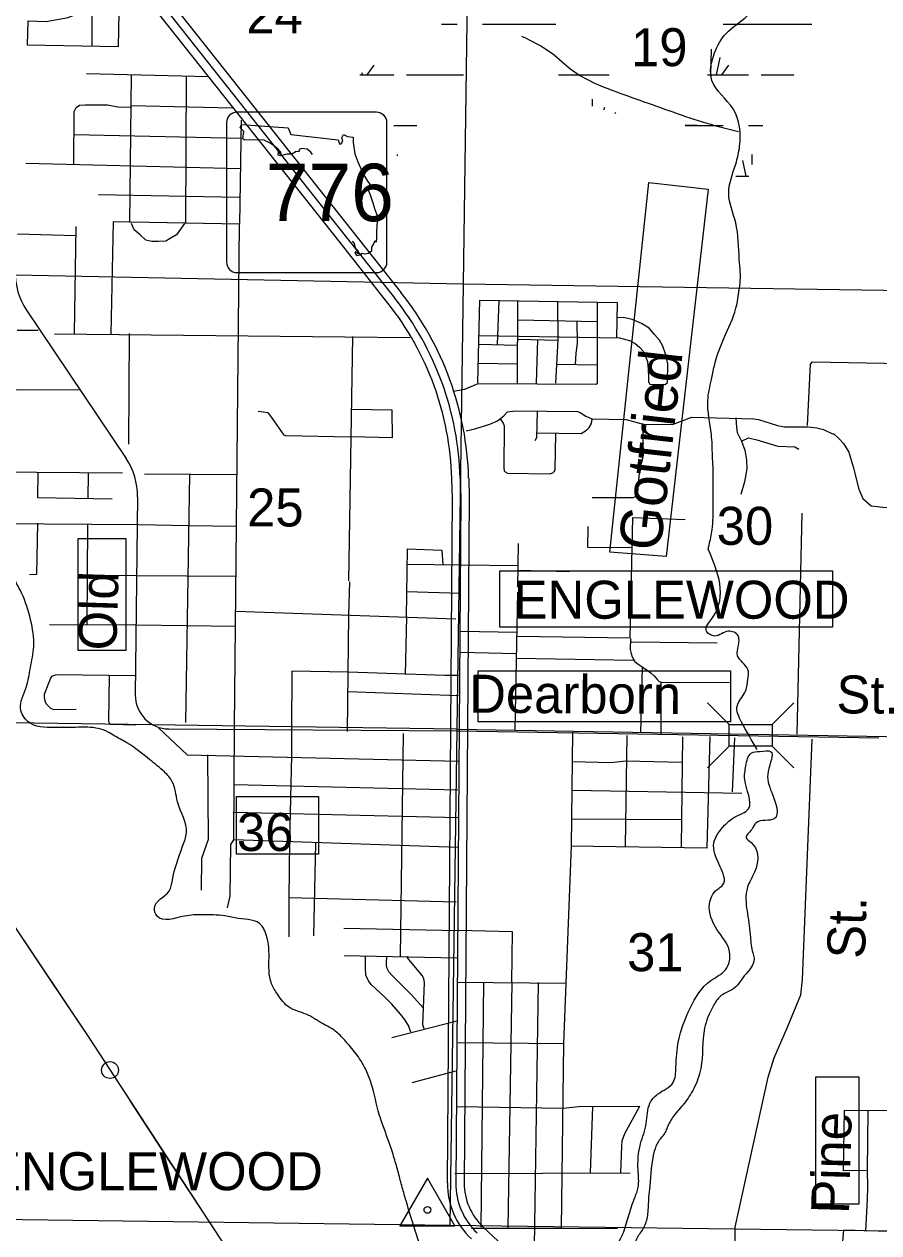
# Model space of a CAD drawing. Extents: x 408847 to 817539, y 923858 to 1151780.
# Drawn here: x 536029 to 546154, y 949646 to 963958 of the extents above; entities that cross this region are included whole.
import ezdxf

# ---------------------------------------------------------------- set-up
doc = ezdxf.new("R2010")
doc.units = 0
for name, color, linetype in [('Bridges', 7, 'Continuous'), ('County Roads Related Text', 7, 'Continuous'), ('County Routes Highway Center Lines', 7, 'Continuous'), ('Interstate Divided Highway Outline and Fill', 7, 'Continuous'), ('Lakes and Ponds', 7, 'Continuous'), ('Level 12', 7, 'Continuous'), ('Level 39', 7, 'Continuous'), ('Level 42', 7, 'Continuous'), ('Level 43', 7, 'Continuous'), ('Level 47', 7, 'Continuous'), ('Level 8', 7, 'Continuous'), ('Local Roads Paved', 7, 'Continuous'), ('Local Roads Related Text', 7, 'Continuous'), ('Masks for Road Features', 7, 'Continuous'), ('Masks for Text', 7, 'Continuous'), ('Narrow River Creek and Branch and Slough', 7, 'Continuous'), ('Roadshields State Highways', 7, 'Continuous'), ('Section Lines', 7, 'Continuous'), ('State Route Divided Highway Outline and Fill', 7, 'Continuous'), ('Swamps', 7, 'Continuous'), ('Township  and Range lines', 7, 'Continuous'), ('Triangulation Station', 7, 'Continuous')]:
    doc.layers.add(name, color=color, linetype=linetype)

msp = doc.modelspace()

# ---------------------------------------------------------------- linework, layer by layer
at = {"layer": 'Bridges'}
for p, q in [((544380, 955664), (544124, 955920)), ((544892, 955664), (545148, 955920)), ((544380, 955408), (544124, 955152)), ((544892, 955408), (545148, 955152))]:
    msp.add_line(p, q, dxfattribs=at)
msp.add_lwpolyline([(544380, 955664), (544892, 955664), (544892, 955408), (544380, 955408)], close=True, dxfattribs=at)
at = {"layer": 'County Routes Highway Center Lines'}
for p, q in [((536058, 960573), (537237, 958817)), ((537372, 958362), (537345, 956018)), ((537742, 955613), (541160, 955591)), ((541160, 955591), (546154, 955508))]:
    msp.add_line(p, q, dxfattribs=at)
for centre, radius, start, end in [((536722, 961019), 800, 179.456, 213.8787), ((536572, 958371), 800, 359.3229, 33.8787), ((537745, 956013), 400, 179.3231, 269.6321)]:
    msp.add_arc(centre, radius, start, end, dxfattribs=at)
at = {"layer": 'Interstate Divided Highway Outline and Fill'}
msp.add_line((537628, 950674), (538022, 950078), dxfattribs=at)
at = {"layer": 'Lakes and Ponds'}
msp.add_line((543180, 949817), (543187, 949839), dxfattribs=at)
for points in [[(540553, 950023), (540508, 950184), (540462, 950356), (540413, 950531), (540353, 950715), (540236, 951046), (540141, 951413), (540080, 951571), (540002, 951707), (539878, 951867), (539771, 951985), (539715, 952035), (539563, 952123), (539369, 952234), (539169, 952316), (539032, 952468), (538960, 952594), (538930, 952752), (538923, 953059), (538868, 953242), (538842, 953286), (538564, 953369), (538406, 953398), (538136, 953413), (537930, 953396), (537604, 953397), (537572, 953497), (537747, 953693), (537785, 953821), (537906, 954223), (537951, 954382), (537846, 954749), (537784, 954987), (537691, 955103), (537519, 955247), (537244, 955449), (537096, 955532), (537022, 955576), (536784, 955633), (536636, 955631), (536384, 955630), (536076, 955697), (535986, 955853), (536051, 956102), (536102, 956335), (536142, 956590), (536105, 956905), (535998, 957224), (535883, 957430), (535725, 957672), (535438, 957944), (535318, 958048), (535147, 958179), (535020, 958179), (534746, 958154), (534522, 958103), (534356, 958096), (534260, 958272), (534127, 958543), (534118, 958852), (534153, 959054), (534163, 959207), (534142, 959434), (534051, 959528)], [(543187, 949839), (543256, 950046), (543303, 950185), (543301, 950388), (543331, 950699), (543399, 950942), (543442, 951181), (543533, 951288), (543717, 951425), (543750, 951606), (543781, 951915), (543918, 952307), (544163, 952633), (544337, 952760), (544386, 952975), (544235, 953239), (544148, 953540), (544238, 953711), (544307, 953765), (544271, 953988), (544200, 954265), (544327, 954472), (544437, 954562), (544609, 954667), (544565, 955014), (544579, 955172), (544642, 955326), (544747, 955346), (544872, 955347), (544842, 955111), (544885, 954860), (544915, 954548), (544699, 954501), (544649, 954422), (544582, 954323), (544640, 954269), (544699, 953962), (544615, 953781), (544588, 953700), (544598, 953422), (544633, 953145), (544660, 952962), (544676, 952900), (544674, 952862), (544541, 952665), (544459, 952558), (544283, 952451), (544190, 952328), (544089, 952069), (544044, 951591), (543961, 951354), (543846, 951177), (543722, 951028), (543647, 950891), (543623, 950837), (543543, 950728), (543493, 950611), (543441, 950198), (543427, 950064), (543414, 949871), (543374, 949720), (543299, 949601), (543259, 949473), (543270, 949292), (543286, 949166), (543316, 949081), (543364, 948951), (543373, 948885), (543331, 948803), (543161, 948790), (543098, 949060), (543078, 949269), (543057, 949486), (543109, 949606), (543180, 949817)], [(540968, 948872), (540816, 949233), (540553, 950023)], [(535300, 949778), (535429, 949564), (535785, 948785), (536682, 946929)]]:
    msp.add_spline(points, degree=3, dxfattribs=at)
at = {"layer": 'Level 12'}
msp.add_circle((537046, 951573), 99.8, dxfattribs=at)
at = {"layer": 'Level 39'}
msp.add_lwpolyline([(541663, 957485), (545606, 957485), (545606, 956817), (541663, 956817)], close=True, dxfattribs=at)
at = {"layer": 'Level 43'}
msp.add_lwpolyline([(542967, 957707), (543430, 962085), (544130, 962003), (543636, 957655)], close=True, dxfattribs=at)
at = {"layer": 'Level 8'}
msp.add_line((541160, 955591), (546154, 955508), dxfattribs=at)
at = {"layer": 'Local Roads Paved'}
for p, q in [((536831, 964150), (536831, 963697)), ((538216, 963334), (536768, 963372)), ((537295, 963359), (537276, 961609)), ((537947, 963341), (537941, 961609)), ((537291, 962995), (538498, 962969)), ((538599, 962605), (536619, 962647)), ((536048, 962312), (538593, 962249)), ((538574, 961905), (536910, 961938)), ((536625, 960297), (536646, 961562)), ((538522, 955639), (538580, 961591)), ((535950, 961476), (536642, 961456)), ((541636, 960165), (541656, 960688)), ((541875, 959709), (541879, 960684)), ((541879, 960456), (542818, 960437)), ((535947, 960333), (536195, 960334)), ((537273, 960295), (537263, 958986)), ((539917, 960258), (539872, 957365)), ((541417, 960171), (541867, 960159)), ((541879, 960229), (542349, 960218)), ((542098, 959709), (542114, 960224)), ((541406, 959944), (541871, 959936)), ((542337, 959932), (542822, 959924)), ((535935, 959632), (536689, 959629)), ((536786, 958343), (536791, 958638)), ((537454, 958634), (538551, 958624)), ((537987, 958627), (537941, 955689)), ((545186, 955549), (545245, 958166)), ((535701, 958044), (537386, 958033)), ((536781, 958032), (536771, 956845)), ((537386, 958033), (537975, 958022)), ((537975, 958022), (538550, 958015)), ((541883, 957809), (541873, 957292)), ((540568, 957563), (541199, 957554)), ((541207, 957556), (541873, 957549)), ((536776, 957435), (537361, 957429)), ((537361, 957429), (538545, 957422)), ((541877, 957491), (542489, 957477)), ((540562, 957239), (541196, 957219)), ((541847, 955604), (541877, 957234)), ((538536, 957007), (541143, 956918)), ((536330, 956848), (537361, 956845)), ((537361, 956845), (538535, 956829)), ((540560, 956939), (540542, 956258)), ((541199, 956769), (541868, 956758)), ((541868, 956713), (543207, 956691)), ((543223, 956646), (544238, 956631)), ((541193, 956523), (541864, 956505)), ((541862, 956452), (543246, 956428)), ((543333, 955568), (543354, 956344)), ((543575, 955553), (543575, 956170)), ((539858, 956054), (541175, 956007)), ((540518, 955559), (540482, 952919)), ((543169, 955536), (543148, 954225)), ((543817, 954218), (543831, 955521)), ((544419, 954866), (544447, 955507)), ((538517, 954953), (541167, 954892)), ((542525, 954887), (544529, 954852)), ((538514, 954626), (541173, 954565)), ((542514, 954549), (543821, 954542)), ((539481, 954261), (539457, 953164)), ((539160, 953618), (541148, 953564)), ((539815, 953255), (541173, 953224)), ((539821, 952930), (541156, 952902)), ((541163, 952615), (542445, 952601)), ((541471, 952612), (541438, 949711)), ((541805, 952608), (541758, 949700)), ((542117, 952608), (542072, 949485)), ((540386, 951959), (541154, 952156)), ((541169, 951898), (542418, 951889)), ((542418, 951889), (542392, 949700)), ((540626, 951426), (541141, 951562)), ((542595, 951140), (543322, 951147)), ((542737, 950354), (542764, 951142)), ((541129, 950350), (543209, 950355))]:
    msp.add_line(p, q, dxfattribs=at)
for points in [[(536903, 964808), (537051, 964580), (537142, 964463), (537153, 964307), (537142, 963691), (536067, 963710), (536075, 963999), (536291, 963991), (536397, 964010), (536549, 964037), (536736, 964113), (536903, 964177), (537047, 964276), (537142, 964352)], [(536619, 962305), (536623, 962923), (536645, 962972), (536684, 962998), (536753, 963004), (537016, 963004), (537139, 962978), (537286, 962975)], [(538599, 962820), (538580, 961591), (537082, 961616), (537057, 960292)], [(537928, 961597), (537834, 961465), (537759, 961421), (537709, 961390), (537621, 961384), (537540, 961384), (537471, 961402), (537402, 961465), (537333, 961522), (537301, 961597)], [(541402, 959713), (541425, 960691), (543053, 960664), (543045, 960246)], [(541116, 959611), (541249, 959638), (541406, 959705), (542807, 959697), (542822, 959709), (542822, 960668)], [(542329, 959709), (542353, 960225), (542349, 960676)], [(541415, 960270), (543080, 960245), (543139, 960229), (543198, 960214), (543268, 960175), (543319, 960132), (543362, 960085), (543386, 960030), (543413, 959963), (543421, 959869), (543425, 959779), (543425, 959724), (543440, 959697), (543624, 959693), (543652, 959716), (543656, 959936), (543632, 960041), (543593, 960147), (543554, 960218), (543495, 960284), (543433, 960359), (543343, 960413), (543233, 960460), (543143, 960480), (543050, 960484)], [(542559, 959928), (542568, 960061), (542583, 960178), (542580, 960437)], [(536390, 960293), (539829, 960254), (540596, 960247)], [(545308, 959206), (545346, 959934), (545368, 959961), (549190, 959890), (549250, 959901), (549283, 959934), (549304, 959983), (549310, 960216), (549293, 960254), (549255, 960281), (549228, 960298), (548957, 960303)], [(539904, 959401), (540385, 959391), (540388, 959059), (539906, 959072)], [(539898, 959068), (539129, 959084), (539108, 959092), (538942, 959328), (538918, 959356), (538800, 959372)], [(541265, 959142), (541366, 959168), (541546, 959223), (541636, 959262), (541711, 959321), (541754, 959368), (541848, 959380), (542583, 959372), (542615, 959360), (542681, 959317), (542752, 959286), (543159, 959278), (543362, 959223), (543710, 959219), (543937, 959305), (544673, 959286), (544728, 959278), (544955, 959204), (545037, 959192), (545315, 959192), (545421, 959180), (545499, 959157), (545612, 959102)], [(541667, 959283), (541703, 959232), (541715, 959200), (541710, 958703), (541717, 958671), (541729, 958658), (541753, 958642), (542258, 958635), (542290, 958644), (542310, 958667), (542320, 958683), (542326, 959109)], [(542105, 959376), (542098, 959061), (542080, 959025)], [(542101, 959120), (542627, 959112), (542660, 959130), (542692, 959152), (542723, 959184), (542748, 959230), (542758, 959282)], [(544459, 959298), (544468, 959181), (544476, 959122), (544525, 959022), (544567, 958914), (544587, 958795), (544590, 958693), (544562, 958539), (544519, 958389)], [(537193, 958642), (534642, 958663), (534614, 958670), (534593, 958683), (534586, 958718), (534597, 959154)], [(543354, 959228), (543361, 958854), (543347, 958779), (543318, 958694), (543297, 958469), (543293, 958402), (543272, 958363), (543240, 958348), (542759, 958348)], [(545617, 959113), (545683, 959048), (545737, 958994), (545797, 958891), (545851, 958717), (545916, 958451), (545965, 958342), (546063, 958255), (546236, 958233), (546508, 958239)], [(544528, 959022), (544610, 959059), (544707, 959037), (544959, 958960), (545158, 958954), (545204, 958926)], [(536189, 958649), (536187, 958355), (537071, 958337)], [(543207, 956691), (543240, 958115), (543860, 958092)], [(536185, 958051), (536176, 957442), (536092, 957437)], [(543233, 957759), (542706, 957762), (542709, 958008)], [(540560, 956939), (540571, 957745), (540978, 957728), (540988, 957557)], [(539881, 957355), (539873, 956958), (539857, 955583)], [(543212, 956685), (543207, 956555), (543220, 956504), (543231, 956466), (543246, 956437), (543262, 956411), (543299, 956383), (543412, 956303), (543455, 956274), (543494, 956240), (543531, 956194), (543551, 956176), (543577, 956166), (544386, 956164)], [(537341, 956241), (536407, 956254), (536375, 956241), (536353, 956232), (536342, 956215), (536266, 956020), (536266, 955983), (536275, 955944), (536290, 955911), (536316, 955881), (536340, 955859), (536379, 955844), (536643, 955846)], [(539866, 956284), (539199, 956297), (539195, 955599)], [(541175, 956245), (541011, 956245), (539866, 956284)], [(537352, 955658), (537057, 955664), (537035, 955684), (537031, 955710), (537040, 956243)], [(537620, 955626), (537960, 955304), (541179, 955232)], [(541173, 954207), (538511, 954300), (538522, 955639)], [(539195, 955599), (539196, 955298), (539172, 954286), (539166, 953606), (539166, 953151)], [(542525, 955575), (542507, 954228), (542418, 951889)], [(542503, 954228), (544120, 954203), (544155, 955525)], [(545071, 952079), (545230, 952465), (545250, 952645), (545363, 955493)], [(538202, 955304), (538208, 954304), (538130, 954079), (538124, 953703)], [(542525, 955226), (542977, 955215), (543158, 955233), (543821, 955218)], [(538507, 954300), (538473, 954246), (538464, 953634), (538432, 953494)], [(541805, 952608), (541814, 953209), (541173, 953227)], [(540611, 952020), (540583, 952102), (540536, 952177), (540489, 952233), (540384, 952355), (540307, 952434), (540141, 952586), (540108, 952628), (540078, 952696), (540071, 952785), (540071, 952926)], [(540758, 952306), (540613, 952467), (540382, 952701), (540349, 952736), (540330, 952774), (540323, 952813), (540323, 952867), (540328, 952920)], [(540768, 952060), (540751, 952107), (540772, 952607), (540765, 952659), (540742, 952692), (540709, 952736), (540585, 952883), (540564, 952916)], [(544444, 948814), (544450, 949714), (544841, 951488), (544915, 951718), (545071, 952079)], [(541159, 951140), (542413, 951122), (542595, 951140)], [(543099, 950355), (543110, 950670), (543115, 950733), (543146, 950822), (543322, 951147)], [(546331, 951090), (545742, 951094), (545731, 950384), (546003, 950388)], [(546025, 951090), (546014, 950388), (546018, 950181), (546014, 950045), (545994, 949671)], [(541328, 949700), (542386, 949700), (543057, 949695)], [(546283, 949663), (545735, 949678), (545720, 949497), (544440, 949506)]]:
    msp.add_lwpolyline(points, dxfattribs=at)
at = {"layer": 'Masks for Road Features'}
msp.add_lwpolyline([(536667, 957867), (537233, 957867), (537233, 956540), (536667, 956540)], close=True, dxfattribs=at)
at = {"layer": 'Masks for Text'}
for points in [[(541406, 956300), (544395, 956300), (544395, 955695), (541406, 955695)], [(538544, 954813), (539514, 954813), (539514, 954129), (538544, 954129)], [(545917, 949983), (545408, 949983), (545408, 951494), (545917, 951494)]]:
    msp.add_lwpolyline(points, close=True, dxfattribs=at)
at = {"layer": 'Narrow River Creek and Branch and Slough'}
for points in [[(527710, 964255), (528070, 963688), (529584, 961690), (531406, 959332), (533921, 956023), (535867, 953345), (536794, 951958), (538709, 949025), (539852, 947287)], [(535840, 953383), (535867, 953345), (536327, 952656)], [(536327, 952656), (536794, 951958), (536813, 951928)], [(537278, 951217), (537756, 950484)], [(537756, 950484), (538235, 949752)]]:
    msp.add_lwpolyline(points, dxfattribs=at)
for points in [[(544501, 960818), (544510, 960883), (544501, 961170), (544458, 961607), (544375, 961952), (544458, 962300), (544505, 962514), (544428, 962954), (544177, 963292), (544208, 963621), (544345, 963848), (544599, 964062), (544782, 964246), (544880, 964312), (544951, 964541), (544970, 964814), (545007, 965146)], [(541921, 963818), (542275, 963619), (542522, 963413), (542944, 963196), (543322, 963058), (543714, 962919), (544115, 962786), (544491, 962686)], [(544172, 959749), (544205, 959912), (544318, 960238), (544461, 960594), (544501, 960818)], [(544182, 958851), (544170, 959101), (544128, 959503), (544172, 959749)], [(544142, 957788), (544179, 957972), (544190, 958269), (544191, 958676), (544182, 958851)], [(544711, 955371), (544528, 955693), (544475, 955884), (544567, 956044), (544602, 956195), (544602, 956318), (544481, 956480), (544487, 956716), (544372, 956770), (544209, 956713), (544111, 956769), (544182, 956928), (544132, 957740)], [(544132, 957740), (544137, 957764), (544142, 957788)]]:
    msp.add_spline(points, degree=3, dxfattribs=at)
at = {"layer": 'Roadshields State Highways'}
for p, q in [((540201, 962916), (538551, 962916)), ((538426, 962791), (538426, 961141)), ((540326, 961141), (540326, 962791)), ((538551, 961016), (540201, 961016))]:
    msp.add_line(p, q, dxfattribs=at)
for points in [[(539446, 962417), (539426, 962442), (539383, 962478), (539314, 962488), (539285, 962475), (539281, 962445), (539252, 962449), (539199, 962419), (539140, 962419), (539064, 962399), (539037, 962406), (539041, 962449), (539057, 962419), (539074, 962435), (539037, 962478), (538981, 962521), (538945, 962551), (538873, 962584), (538797, 962587), (538642, 962584), (538619, 962600), (538632, 962686), (538586, 962729), (538602, 962769)], [(538602, 962769), (539156, 962729), (539186, 962650), (539749, 962587), (539763, 962541), (539786, 962541), (539802, 962574), (539792, 962614), (539812, 962653), (539861, 962630), (539927, 962620), (539927, 962557), (539947, 962422), (539980, 962327), (540049, 962178), (540096, 962099), (540122, 962063), (540102, 962007), (540128, 961937), (540161, 961842), (540185, 961763), (540211, 961693), (540211, 961631), (540204, 961505), (540201, 961433), (540198, 961377), (540185, 961393), (540168, 961357), (540145, 961317), (540145, 961271), (540105, 961241), (540063, 961235), (540026, 961241), (540013, 961222), (539970, 961215), (539950, 961251), (539960, 961268), (539974, 961245), (539990, 961238), (539990, 961268), (539954, 961311), (539941, 961363), (539918, 961388)]]:
    msp.add_lwpolyline(points, dxfattribs=at)
for centre, start, end in [((538551, 962791), 90, 180), ((540201, 962791), 0, 90), ((538551, 961141), 180, 270), ((540201, 961141), 270, 0)]:
    msp.add_arc(centre, 125, start, end, dxfattribs=at)
at = {"layer": 'Section Lines'}
for p, q in [((535925, 960991), (541228, 960882)), ((541228, 960882), (546579, 960805)), ((541153, 955609), (535869, 955685)), ((541153, 955609), (546511, 955518)), ((541070, 949733), (535332, 949809)), ((546283, 949665), (541070, 949733))]:
    msp.add_line(p, q, dxfattribs=at)
at = {"layer": 'State Route Divided Highway Outline and Fill'}
for p, q in [((539771, 961372), (533502, 969280)), ((533581, 969342), (539849, 961434)), ((533659, 969404), (539927, 961496)), ((539849, 961434), (540418, 960716)), ((539927, 961496), (540496, 960778)), ((540339, 960654), (539771, 961372)), ((541102, 958342), (541095, 958578)), ((541195, 958580), (541202, 958345)), ((541295, 958583), (541295, 958583)), ((541295, 958583), (541302, 958347)), ((541042, 950236), (541102, 958345)), ((541102, 958345), (541102, 958342)), ((541202, 958345), (541142, 950235)), ((541302, 958344), (541242, 950234)), ((541302, 958347), (541302, 958344)), ((541242, 950234), (541242, 950234)), ((541463, 949718), (541902, 949307))]:
    msp.add_line(p, q, dxfattribs=at)
for centre, radius, start, end in [((537596, 958480), 3600, 1.598, 38.3997), ((537596, 958480), 3700, 1.598, 38.3997), ((537596, 958480), 3500, 1.598, 38.3997), ((541942, 950229), 900, 179.5792, 226.8345), ((541942, 950229), 800, 179.5792, 226.8345), ((541942, 950229), 700, 179.5792, 226.8345)]:
    msp.add_arc(centre, radius, start, end, dxfattribs=at)
at = {"layer": 'Swamps'}
for p, q in [((544308, 963958), (545358, 963958)), ((544164, 963358), (544170, 963662)), ((544231, 963358), (544274, 963564)), ((544294, 963358), (544377, 963472)), ((542358, 963358), (542958, 963358)), ((544125, 963358), (544608, 963358)), ((543858, 962758), (544308, 962758)), ((544540, 962344), (544577, 962158))]:
    msp.add_line(p, q, dxfattribs=at)
for points in [[(540971, 963958), (541158, 963958)], [(541458, 963958), (542328, 963958)], [(540094, 963358), (540177, 963472)], [(540004, 963358), (540408, 963358)], [(540031, 963358), (540037, 963386)], [(540558, 963358), (541233, 963358)], [(544758, 963358), (545145, 963358)], [(542757, 963069), (542757, 962986)], [(542902, 962973), (542893, 962940)], [(543035, 962912), (543025, 962896)], [(540408, 962758), (540679, 962758)], [(544000, 962758), (543858, 962758)], [(544608, 962758), (544780, 962758)], [(540449, 962417), (540449, 962398)], [(544649, 962417), (544649, 962298)], [(544458, 962158), (544613, 962158)]]:
    msp.add_lwpolyline(points, dxfattribs=at)
at = {"layer": 'Township  and Range lines'}
for p, q in [((541304, 966222), (541228, 960882)), ((541228, 960882), (541153, 955609)), ((541153, 955609), (541070, 949733))]:
    msp.add_line(p, q, dxfattribs=at)
at = {"layer": 'Triangulation Station'}
msp.add_lwpolyline([(540806, 950293), (540481, 949730), (541131, 949730)], close=True, dxfattribs=at)
msp.add_circle((540806, 949917), 40, dxfattribs=at)

# ---------------------------------------------------------------- texts
at = {"layer": 'County Roads Related Text'}
for s, rotation, p in [('Old', 88.264, (537120, 956537)), ('Dearborn', 359.6689, (541300, 955805)), ('St.', 359.6689, (545651, 955797))]:
    msp.add_text(s, height=450, rotation=rotation, dxfattribs=at).set_placement(p)
at = {"layer": 'Level 39'}
msp.add_text('ENGLEWOOD', height=450, rotation=0, dxfattribs=at).set_placement((541828, 956918))
at = {"layer": 'Level 42'}
msp.add_text('Gotfried', height=500, rotation=83.6053, dxfattribs=at).set_placement((543566, 957706))
at = {"layer": 'Level 43'}
for s, p in [('24', (538661, 963849)), ('19', (543218, 963461)), ('25', (538670, 958010)), ('30', (544233, 957793)), ('36', (538549, 954167)), ('31', (543172, 952744))]:
    msp.add_text(s, height=450, rotation=0, dxfattribs=at).set_placement(p)
at = {"layer": 'Level 47'}
msp.add_text('ENGLEWOOD', height=450, rotation=0.0001, dxfattribs=at).set_placement((535588, 950150))
at = {"layer": 'Local Roads Related Text'}
for s, p in [('St.', (545989, 952887)), ('Pine', (545800, 949866))]:
    msp.add_text(s, height=450, rotation=88.3862, dxfattribs=at).set_placement(p)
at = {"layer": 'Roadshields State Highways'}
msp.add_text('776', height=680, dxfattribs=at).set_placement((538891, 961626))

doc.saveas('drawing.dxf')
